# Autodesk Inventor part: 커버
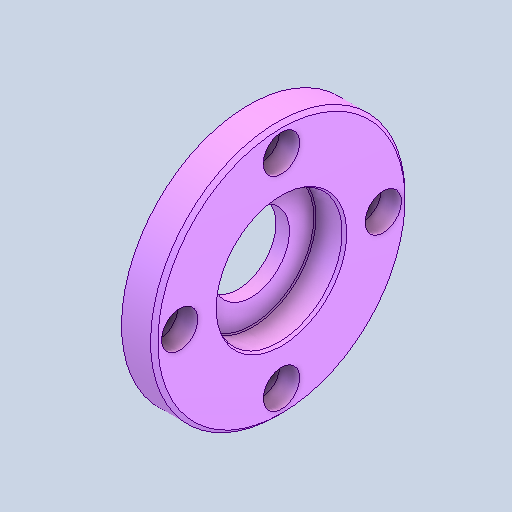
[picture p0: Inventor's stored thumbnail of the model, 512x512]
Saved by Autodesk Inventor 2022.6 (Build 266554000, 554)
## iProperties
Created: 2024-09
Part Number: 커버
Material: 알루미늄 6061
Document SubType Name: Modeling
Designer: Class 001
Density: 2.7 g/cm^3
Appearance: 기본값
Author: jhkim
Sending System: Autodesk Inventor 2025
Preprocessor: ST-DEVELOPER v20
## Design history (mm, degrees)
feature "솔리드1"
node "솔리드2"
